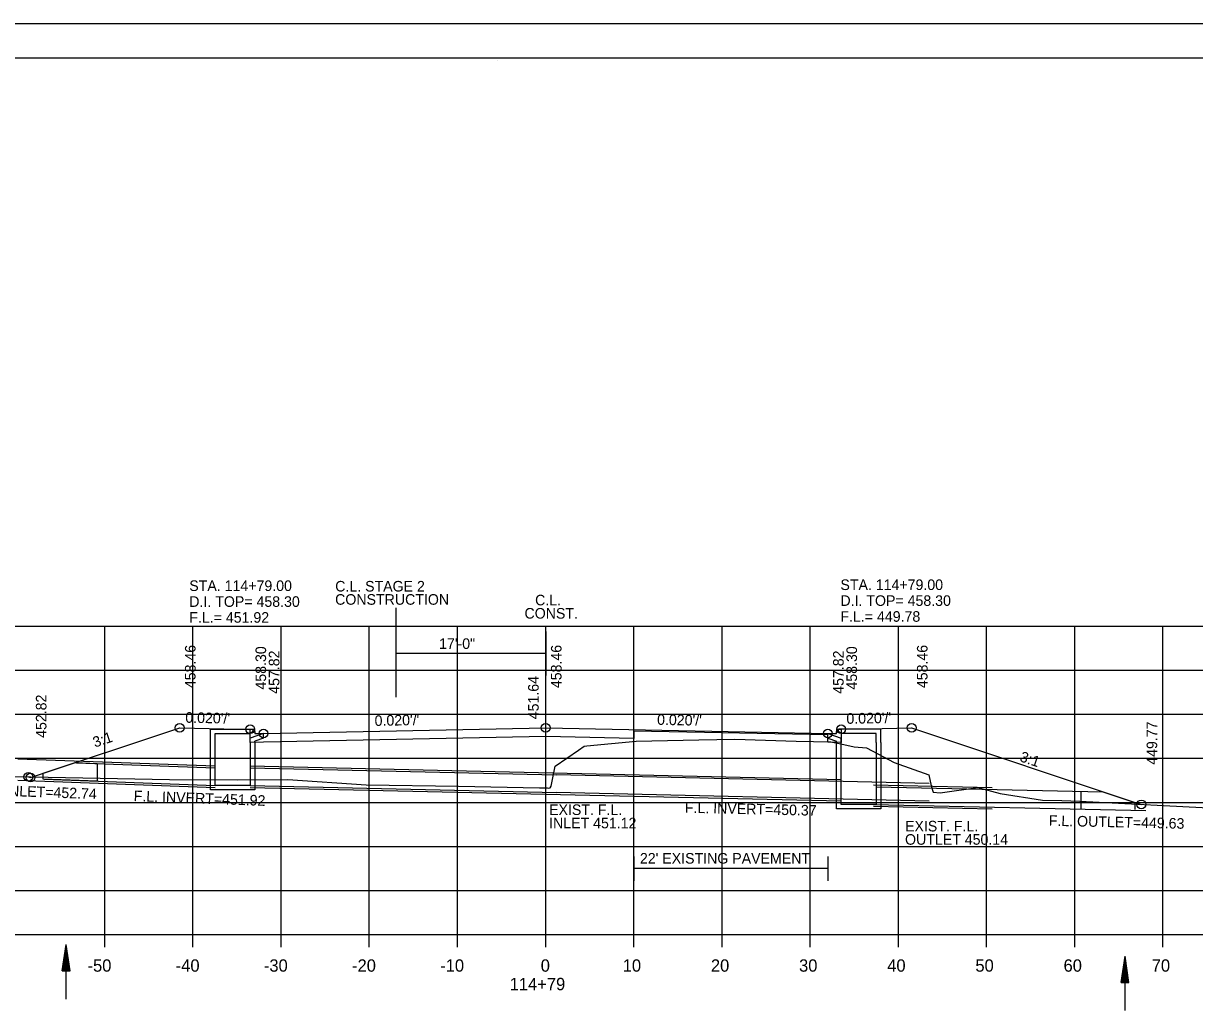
# Model space of a CAD drawing. Extents: x 1538688 to 1540766, y 656250 to 671912.
# Drawn here: x 1538798.9 to 1538931.8, y 658572.5 to 658684.6 of the extents above; entities that cross this region are included whole.
import ezdxf

# ---------------------------------------------------------------- set-up
doc = ezdxf.new("R2010")
doc.units = 0
for name, color, linetype in [('15', 7, 'Continuous'), ('18', 7, 'Continuous'), ('20', 7, 'Continuous'), ('22', 7, 'Continuous'), ('26', 7, 'Continuous'), ('39', 7, 'Continuous'), ('40', 7, 'Continuous'), ('41', 7, 'Continuous'), ('42', 7, 'Continuous'), ('7', 7, 'Continuous'), ('Borings', 7, 'Continuous'), ('Default', 7, 'Continuous'), ('Horizontal Alignment', 7, 'Continuous'), ('RipRap', 7, 'Continuous'), ('Wall Heights', 7, 'Continuous')]:
    doc.layers.add(name, color=color, linetype=linetype)

msp = doc.modelspace()

# ---------------------------------------------------------------- linework, layer by layer
at = {"layer": '15'}
for p, q in [((1538803.33, 658577.14), (1538803.78, 658580.14)), ((1538803.41, 658577.14), (1538803.78, 658579.64)), ((1538804.23, 658577.14), (1538803.78, 658580.14)), ((1538804.16, 658577.14), (1538803.78, 658579.64)), ((1538803.48, 658577.14), (1538803.78, 658579.12)), ((1538803.56, 658577.14), (1538803.78, 658578.62)), ((1538803.64, 658577.14), (1538803.78, 658578.11)), ((1538804.08, 658577.14), (1538803.78, 658579.12)), ((1538804, 658577.14), (1538803.78, 658578.62)), ((1538803.93, 658577.14), (1538803.78, 658578.11)), ((1538923.44, 658575.83), (1538923.89, 658578.83)), ((1538923.51, 658575.83), (1538923.89, 658578.33)), ((1538924.34, 658575.83), (1538923.89, 658578.83)), ((1538924.26, 658575.83), (1538923.89, 658578.33)), ((1538803.33, 658577.14), (1538804.23, 658577.14)), ((1538803.71, 658577.14), (1538803.78, 658577.61)), ((1538803.85, 658577.14), (1538803.78, 658577.61)), ((1538923.59, 658575.83), (1538923.89, 658577.81)), ((1538923.66, 658575.83), (1538923.89, 658577.32)), ((1538923.74, 658575.83), (1538923.89, 658576.81)), ((1538924.19, 658575.83), (1538923.89, 658577.81)), ((1538924.11, 658575.83), (1538923.89, 658577.32)), ((1538924.04, 658575.83), (1538923.89, 658576.81)), ((1538923.44, 658575.83), (1538924.34, 658575.83)), ((1538923.82, 658575.83), (1538923.89, 658576.31)), ((1538923.96, 658575.83), (1538923.89, 658576.31))]:
    msp.add_line(p, q, dxfattribs=at)
at = {"layer": '18'}
msp.add_lwpolyline([(1538789.92, 658599.36), (1538815.53, 658598.84), (1538823.23, 658598.83), (1538828.94, 658598.85), (1538837.82, 658598.27), (1538848.28, 658598.11), (1538857.48, 658597.9), (1538858.39, 658597.9), (1538858.54, 658597.87), (1538858.69, 658597.91), (1538858.8, 658598.11), (1538859.26, 658600.37), (1538861.9, 658602.19), (1538862.56, 658602.63), (1538862.86, 658602.66), (1538868.45, 658603.21), (1538875.54, 658603.35), (1538879.64, 658603.42), (1538886.6, 658603.22), (1538890.53, 658603.13), (1538891.66, 658602.9), (1538893.17, 658602.58), (1538894.55, 658602.45), (1538897.72, 658600.77), (1538901.63, 658599.38), (1538901.91, 658598.14), (1538902.14, 658597.41), (1538902.92, 658597.33), (1538907.18, 658597.95), (1538909.72, 658597.26), (1538914.53, 658596.53), (1538916.72, 658596.49), (1538918.78, 658596.39), (1538934.84, 658595.56)], dxfattribs=at)
at = {"layer": '20'}
msp.add_lwpolyline([(1538799.51, 658599.16), (1538799.76, 658599.08), (1538816.67, 658604.72), (1538821.67, 658604.62), (1538824.67, 658604.56), (1538825.17, 658604.56), (1538825.18, 658604.06), (1538826.18, 658604.08), (1538858.18, 658604.72), (1538890.18, 658604.08), (1538891.18, 658604.06), (1538891.19, 658604.56), (1538891.69, 658604.56), (1538894.69, 658604.62), (1538899.69, 658604.72), (1538925.74, 658596.03)], dxfattribs=at)
at = {"layer": '22'}
for p, q in [((1538718.18, 658616.26), (1538998.18, 658616.26)), ((1538808.18, 658581.26), (1538808.18, 658616.26)), ((1538818.18, 658581.26), (1538818.18, 658616.26)), ((1538828.18, 658581.26), (1538828.18, 658616.26)), ((1538838.18, 658581.26), (1538838.18, 658616.26)), ((1538848.18, 658581.26), (1538848.18, 658616.26)), ((1538858.18, 658581.26), (1538858.18, 658616.26)), ((1538868.18, 658581.26), (1538868.18, 658616.26)), ((1538878.18, 658581.26), (1538878.18, 658616.26)), ((1538888.18, 658581.26), (1538888.18, 658616.26)), ((1538898.18, 658581.26), (1538898.18, 658616.26)), ((1538908.18, 658581.26), (1538908.18, 658616.26)), ((1538918.18, 658581.26), (1538918.18, 658616.26)), ((1538928.18, 658581.26), (1538928.18, 658616.26)), ((1538718.18, 658611.26), (1538998.18, 658611.26)), ((1538718.18, 658606.26), (1538998.18, 658606.26)), ((1538718.18, 658601.26), (1538998.18, 658601.26)), ((1538718.18, 658596.26), (1538998.18, 658596.26)), ((1538718.18, 658591.26), (1538998.18, 658591.26)), ((1538718.18, 658586.26), (1538998.18, 658586.26)), ((1538718.18, 658581.26), (1538998.18, 658581.26))]:
    msp.add_line(p, q, dxfattribs=at)
at = {"layer": '26'}
for p, q in [((1538687.78, 658684.61), (1539021.11, 658684.61)), ((1538798.32, 658601.21), (1538820.68, 658600.39)), ((1538824.68, 658600.39), (1538891.68, 658598.84)), ((1538798.32, 658598.79), (1538820.68, 658597.97)), ((1538895.35, 658598.25), (1538908.82, 658597.95)), ((1538824.68, 658597.97), (1538891.68, 658596.42)), ((1538895.35, 658595.83), (1538908.82, 658595.53))]:
    msp.add_line(p, q, dxfattribs=at)
msp.add_lwpolyline([(1538687.77, 658684.61), (1539021.11, 658684.61), (1539021.11, 658471.28), (1538687.77, 658471.28)], close=True, dxfattribs=at)
for centre in [(1538816.67, 658604.72), (1538824.67, 658604.56), (1538858.18, 658604.72), (1538891.69, 658604.56), (1538899.69, 658604.72), (1538826.18, 658604.08), (1538890.18, 658604.08), (1538799.51, 658599.16), (1538799.76, 658599.08), (1538925.74, 658596.03)]:
    msp.add_circle(centre, 0.5, dxfattribs=at)
at = {"layer": '39'}
for p, q in [((1538820.18, 658604.56), (1538824.93, 658604.56)), ((1538820.18, 658603.06), (1538820.18, 658604.56)), ((1538820.68, 658603.06), (1538820.68, 658604.06)), ((1538820.68, 658604.06), (1538824.68, 658604.06)), ((1538825.01, 658604.39), (1538824.68, 658604.06)), ((1538826.18, 658604.08), (1538824.68, 658603.56)), ((1538824.68, 658603.06), (1538824.68, 658603.56)), ((1538825.01, 658604.39), (1538824.93, 658604.56)), ((1538826.18, 658603.55), (1538825.18, 658603.2)), ((1538890.18, 658604.08), (1538891.68, 658603.56)), ((1538890.18, 658603.55), (1538891.18, 658603.2)), ((1538891.34, 658604.39), (1538891.43, 658604.56)), ((1538891.34, 658604.39), (1538891.68, 658604.06)), ((1538896.18, 658604.56), (1538891.43, 658604.56)), ((1538895.68, 658604.06), (1538891.68, 658604.06)), ((1538891.68, 658603.06), (1538891.68, 658603.56)), ((1538895.68, 658603.06), (1538895.68, 658604.06)), ((1538896.18, 658603.06), (1538896.18, 658604.56)), ((1538825.18, 658603.06), (1538825.18, 658603.2)), ((1538891.18, 658603.06), (1538891.18, 658603.2)), ((1538804.95, 658600.76), (1538820.68, 658600.18)), ((1538824.68, 658600.18), (1538859.42, 658599.38)), ((1538801.32, 658598.89), (1538820.68, 658598.18)), ((1538824.68, 658598.18), (1538859.43, 658597.38)), ((1538918.89, 658597.49), (1538918.89, 658595.55)), ((1538895.35, 658596.04), (1538926.25, 658595.34)), ((1538925.02, 658596.28), (1538925.02, 658595.45)), ((1538803.78, 658573.95), (1538803.78, 658580.14)), ((1538923.89, 658572.64), (1538923.89, 658578.83))]:
    msp.add_line(p, q, dxfattribs=at)
for points in [[(1538826.18, 658603.55), (1538826.18, 658604.08)], [(1538890.18, 658603.55), (1538890.18, 658604.08)], [(1538825.18, 658603.06), (1538825.18, 658597.68), (1538822.68, 658597.68), (1538820.18, 658597.68), (1538820.18, 658603.06)], [(1538824.68, 658603.06), (1538824.68, 658598.18), (1538822.68, 658598.18), (1538820.68, 658598.18), (1538820.68, 658603.06)], [(1538896.18, 658603.06), (1538896.18, 658595.54), (1538893.68, 658595.54), (1538891.18, 658595.54), (1538891.18, 658603.06)], [(1538895.68, 658603.06), (1538895.68, 658596.04), (1538893.68, 658596.04), (1538891.68, 658596.04), (1538891.68, 658603.06)], [(1538901.68, 658598.4), (1538859.42, 658599.38)], [(1538895.68, 658598.03), (1538921.39, 658597.46), (1538925.02, 658596.25)], [(1538901.68, 658596.4), (1538901.68, 658596.4), (1538859.38, 658597.38)]]:
    msp.add_lwpolyline(points, dxfattribs=at)
msp.add_lwpolyline([(1538801.19, 658598.89), (1538801.19, 658599.56), (1538804.82, 658600.77), (1538807.32, 658600.68), (1538807.32, 658598.68)], close=True, dxfattribs=at)
at = {"layer": '7'}
for p, q in [((1538868.17, 658590.13), (1538868.17, 658587.38)), ((1538890.17, 658590.13), (1538890.17, 658587.38)), ((1538890.17, 658588.76), (1538868.17, 658588.76))]:
    msp.add_line(p, q, dxfattribs=at)
at = {"layer": 'Borings'}
for p, q in [((1538718.18, 658581.26), (1538998.18, 658581.26)), ((1538808.18, 658579.86), (1538808.18, 658581.26)), ((1538818.18, 658579.86), (1538818.18, 658581.26)), ((1538828.18, 658579.86), (1538828.18, 658581.26)), ((1538838.18, 658579.86), (1538838.18, 658581.26)), ((1538848.18, 658579.86), (1538848.18, 658581.26)), ((1538858.18, 658579.86), (1538858.18, 658581.26)), ((1538868.18, 658579.86), (1538868.18, 658581.26)), ((1538878.18, 658579.86), (1538878.18, 658581.26)), ((1538888.18, 658579.86), (1538888.18, 658581.26)), ((1538898.18, 658579.86), (1538898.18, 658581.26)), ((1538908.18, 658579.86), (1538908.18, 658581.26)), ((1538918.18, 658579.86), (1538918.18, 658581.26)), ((1538928.18, 658579.86), (1538928.18, 658581.26))]:
    msp.add_line(p, q, dxfattribs=at)
at = {"layer": 'Default'}
for p, q in [((1538841.17, 658618.34), (1538841.17, 658608.18)), ((1538858.18, 658615.66), (1538858.18, 658610.66)), ((1538858.18, 658613.16), (1538841.17, 658613.16))]:
    msp.add_line(p, q, dxfattribs=at)
at = {"layer": 'RipRap'}
for p, q in [((1538700.18, 658680.72), (1539016.36, 658680.72)), ((1538852.7, 658680.46), (1538852.7, 658680.46)), ((1538852.7, 658680.46), (1538852.7, 658680.46))]:
    msp.add_line(p, q, dxfattribs=at)
at = {"layer": 'Wall Heights'}
msp.add_lwpolyline([(1538891.69, 658604.56), (1538891.69, 658603.06), (1538890.18, 658603.08), (1538890.17, 658603.08), (1538890.17, 658603.91), (1538868.17, 658604.35), (1538868.17, 658603.52), (1538858.18, 658603.72), (1538826.18, 658603.08), (1538824.67, 658603.06), (1538824.67, 658604.56)], dxfattribs=at)

# ---------------------------------------------------------------- texts
at = {"layer": '40'}
for s, p in [('STA. 114+79.00', (1538817.76, 658620.24)), ('STA. 114+79.00', (1538891.61, 658620.35)), ('D.I. TOP= 458.30', (1538817.76, 658618.44)), ('D.I. TOP= 458.30', (1538891.61, 658618.55)), ('F.L.= 449.78', (1538891.61, 658616.75)), ('F.L.= 451.92', (1538817.76, 658616.64)), ('EXIST. F.L.', (1538858.57, 658594.83)), ('INLET 451.12', (1538858.57, 658593.32)), ('EXIST. F.L.', (1538898.94, 658592.97)), ('OUTLET 450.14', (1538898.94, 658591.46))]:
    msp.add_text(s, height=1.2, dxfattribs=at).set_placement(p)
for s, rotation, p in [('F.L. INLET=452.74', 357.8986, (1538793.65, 658597.12)), ('F.L. INVERT=451.92', 357.8986, (1538811.44, 658596.41)), ('F.L. INVERT=450.37', 358.6747, (1538873.96, 658595.09)), ('F.L. OUTLET=449.63', 358.7092, (1538915.23, 658593.61))]:
    msp.add_text(s, height=1.2, rotation=rotation, dxfattribs=at).set_placement(p)
at = {"layer": '41'}
for s, p in [('458.46', (1538818.47, 658609.22)), ('458.46', (1538859.98, 658609.22)), ('458.46', (1538901.49, 658609.22)), ('458.30', (1538826.47, 658609.06)), ('457.82', (1538827.98, 658608.58)), ('457.82', (1538891.98, 658608.58)), ('458.30', (1538893.49, 658609.06)), ('451.64', (1538857.39, 658605.69)), ('452.82', (1538801.56, 658603.58)), ('449.77', (1538927.54, 658600.53))]:
    msp.add_text(s, height=1.2, rotation=90, dxfattribs=at).set_placement(p)
at = {"layer": '42'}
for s, rotation, p in [("0.020'/'", 358.8542, (1538817.3, 658605.3)), ("0.020'/'", 1.1458, (1538838.79, 658604.93)), ("0.020'/'", 358.8542, (1538870.81, 658605.06)), ("0.020'/'", 1.1458, (1538892.3, 658605.17)), ('3:1', 18.4349, (1538807.05, 658602.47)), ('3:1', 341.5651, (1538911.87, 658600.95))]:
    msp.add_text(s, height=1.2, rotation=rotation, dxfattribs=at).set_placement(p)
at = {"layer": '7'}
msp.add_text("22' EXISTING PAVEMENT", height=1.2, dxfattribs=at).set_placement((1538868.87, 658589.32))
at = {"layer": 'Default'}
for s, p in [('C.L. STAGE 2', (1538834.31, 658620.18)), ('CONSTRUCTION', (1538834.3, 658618.68)), ('C.L.', (1538856.98, 658618.61)), ('CONST.', (1538855.78, 658617.11)), ('17\'-0"', (1538846.09, 658613.67))]:
    msp.add_text(s, height=1.2, dxfattribs=at).set_placement(p)
at = {"layer": 'Horizontal Alignment'}
for s, p in [('-50', (1538806.22, 658577.06)), ('-40', (1538816.22, 658577.06)), ('-30', (1538826.22, 658577.06)), ('-20', (1538836.22, 658577.06)), ('-10', (1538846.22, 658577.06)), ('0', (1538857.62, 658577.06)), ('10', (1538866.92, 658577.06)), ('20', (1538876.92, 658577.06)), ('30', (1538886.92, 658577.06)), ('40', (1538896.92, 658577.06)), ('50', (1538906.92, 658577.06)), ('60', (1538916.92, 658577.06)), ('70', (1538926.92, 658577.06)), ('114+79', (1538854.1, 658574.96))]:
    msp.add_text(s, height=1.4, dxfattribs=at).set_placement(p)

doc.saveas('drawing.dxf')
